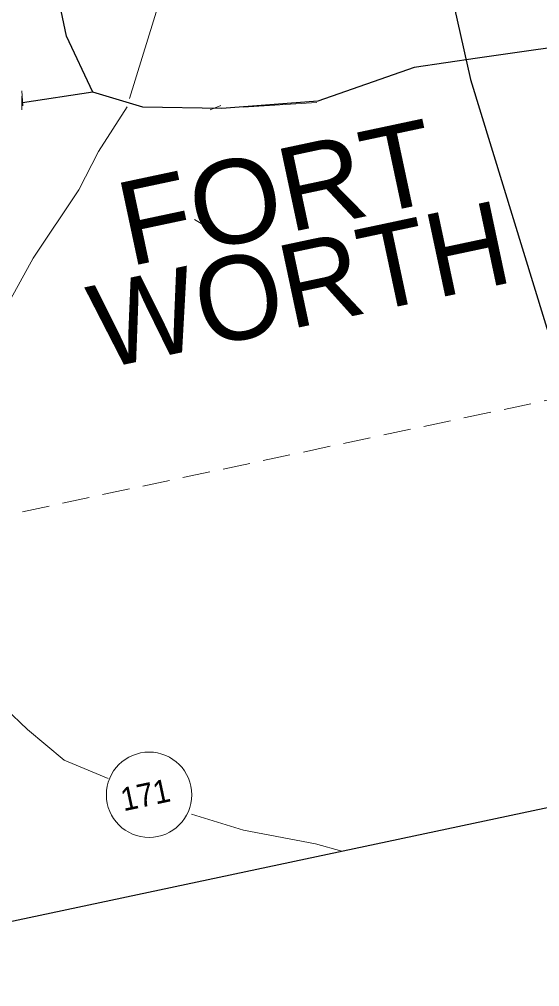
# Model space of a CAD drawing. Extents: x 2357218 to 2371708, y 6973728 to 6980157.
# Drawn here: x 2357408.8 to 2357522.9, y 6974407.9 to 6974620.2 of the extents above; entities that cross this region are included whole.
import ezdxf

# ---------------------------------------------------------------- set-up
doc = ezdxf.new("R2010")
doc.units = 0
doc.header["$LTSCALE"] = 2
doc.linetypes.add('MEDIUM_DASHED', pattern=[4.5, 3, -1.5])
doc.layers.add('62', color=7, linetype='Continuous', lineweight=13)
doc.layers.add('63', color=7, linetype='Continuous', lineweight=13)

msp = doc.modelspace()

# ---------------------------------------------------------------- linework, layer by layer
at = {"layer": '62'}
for p, q in [((2357440.151, 6974626.169), (2357432.971, 6974602.904)), ((2357409.331, 6974604.592), (2357409.526, 6974601.301)), ((2357409.315, 6974603.372), (2357409.369, 6974600.416)), ((2357450.639, 6974600.423), (2357452.946, 6974601.374)), ((2357474.001, 6974601.984), (2357457.839, 6974600.965)), ((2357449.732, 6974574.81), (2357447.205, 6974576.321)), ((2357410.579, 6974464.416), (2357418.634, 6974457.686)), ((2357418.634, 6974457.686), (2357428.242, 6974453.609)), ((2357457.93, 6974442.297), (2357446.564, 6974445.791))]:
    msp.add_line(p, q, dxfattribs=at)
at = {"layer": '62', "lineweight": 25}
msp.add_line((2357424.93, 6974604.275), (2357409.493, 6974601.89), dxfattribs=at)
at = {"layer": '62', "linetype": 'MEDIUM_DASHED'}
msp.add_line((2357321.423, 6974493.477), (2357761.192, 6974586.953), dxfattribs=at)
at = {"layer": '62', "lineweight": 25}
for points in [[(2357242.867, 6974863.05), (2357339.603, 6974407.945), (2357779.37, 6974501.42), (2357682.634, 6974956.528)], [(2357484.401, 6974709.004), (2357495.501, 6974661.441), (2357507.761, 6974607.022), (2357528.73, 6974538.67), (2357551.355, 6974511.341)], [(2357596.715, 6974637.66), (2357589.374, 6974634.536), (2357579.785, 6974631.6), (2357566.27, 6974627.645), (2357556.498, 6974625.57), (2357549.681, 6974623.223), (2357545.38, 6974619.435), (2357535.992, 6974615.437), (2357522.037, 6974613.553), (2357509.283, 6974611.762), (2357495.348, 6974609.674), (2357474.275, 6974602.318), (2357453.198, 6974600.715), (2357435.858, 6974601.009), (2357424.93, 6974604.275), (2357419.167, 6974616.556), (2357416.416, 6974629.495), (2357413.211, 6974635.486), (2357416.135, 6974645.654)]]:
    msp.add_lwpolyline(points, dxfattribs=at)
at = {"layer": '62'}
for points in [[(2357432.423, 6974601.035), (2357426.152, 6974591.262), (2357421.824, 6974582.844), (2357411.809, 6974567.829), (2357403.224, 6974552.273)], [(2357309.219, 6974550.9), (2357313.892, 6974547.2), (2357327.315, 6974535.032), (2357335.518, 6974519.384), (2357342.091, 6974506.75), (2357351.934, 6974500.263), (2357369.659, 6974490.04), (2357379.731, 6974485.624), (2357395.823, 6974478.418), (2357410.579, 6974464.416)], [(2357457.93, 6974442.297), (2357473.727, 6974439.306), (2357479.502, 6974437.68)]]:
    msp.add_lwpolyline(points, dxfattribs=at)
msp.add_circle((2357437.237, 6974450.059), 9.364, dxfattribs=at)
at = {"layer": '63'}
for p, q in [((2357440.151, 6974626.169), (2357432.971, 6974602.904)), ((2357409.331, 6974604.592), (2357409.526, 6974601.301)), ((2357409.315, 6974603.372), (2357409.369, 6974600.416)), ((2357450.639, 6974600.423), (2357452.946, 6974601.374)), ((2357474.001, 6974601.984), (2357457.839, 6974600.965)), ((2357449.732, 6974574.81), (2357447.205, 6974576.321)), ((2357410.579, 6974464.416), (2357418.634, 6974457.686)), ((2357418.634, 6974457.686), (2357428.242, 6974453.609)), ((2357457.93, 6974442.297), (2357446.564, 6974445.791))]:
    msp.add_line(p, q, dxfattribs=at)
at = {"layer": '63', "lineweight": 25}
msp.add_line((2357424.93, 6974604.275), (2357409.493, 6974601.89), dxfattribs=at)
at = {"layer": '63', "linetype": 'MEDIUM_DASHED'}
msp.add_line((2357321.423, 6974493.477), (2357761.192, 6974586.953), dxfattribs=at)
at = {"layer": '63', "lineweight": 25}
for points in [[(2357242.867, 6974863.05), (2357339.603, 6974407.945), (2357779.37, 6974501.42), (2357682.634, 6974956.528)], [(2357484.401, 6974709.004), (2357495.501, 6974661.441), (2357507.761, 6974607.022), (2357528.73, 6974538.67), (2357551.355, 6974511.341)], [(2357596.715, 6974637.66), (2357589.374, 6974634.536), (2357579.785, 6974631.6), (2357566.27, 6974627.645), (2357556.498, 6974625.57), (2357549.681, 6974623.223), (2357545.38, 6974619.435), (2357535.992, 6974615.437), (2357522.037, 6974613.553), (2357509.283, 6974611.762), (2357495.348, 6974609.674), (2357474.275, 6974602.318), (2357453.198, 6974600.715), (2357435.858, 6974601.009), (2357424.93, 6974604.275), (2357419.167, 6974616.556), (2357416.416, 6974629.495), (2357413.211, 6974635.486), (2357416.135, 6974645.654)]]:
    msp.add_lwpolyline(points, dxfattribs=at)
at = {"layer": '63'}
for points in [[(2357432.423, 6974601.035), (2357426.152, 6974591.262), (2357421.824, 6974582.844), (2357411.809, 6974567.829), (2357403.224, 6974552.273)], [(2357309.219, 6974550.9), (2357313.892, 6974547.2), (2357327.315, 6974535.032), (2357335.518, 6974519.384), (2357342.091, 6974506.75), (2357351.934, 6974500.263), (2357369.659, 6974490.04), (2357379.731, 6974485.624), (2357395.823, 6974478.418), (2357410.579, 6974464.416)], [(2357457.93, 6974442.297), (2357473.727, 6974439.306), (2357479.502, 6974437.68)]]:
    msp.add_lwpolyline(points, dxfattribs=at)
msp.add_circle((2357437.237, 6974450.059), 9.364, dxfattribs=at)

# ---------------------------------------------------------------- texts
at = {"layer": '62'}
for s, height, width, p in [('FORT', 18.39, 1.05, (2357432.817, 6974565.97)), ('171', 5.099, 0.95, (2357431.657, 6974446.423))]:
    msp.add_text(s, height=height, rotation=12, dxfattribs=dict(at, width=width)).set_placement(p)
msp.add_text('WORTH', height=18.39, rotation=12, dxfattribs=at).set_placement((2357426.733, 6974543.398))
at = {"layer": '63'}
for s, height, width, p in [('FORT', 18.39, 1.05, (2357432.817, 6974565.97)), ('171', 5.099, 0.95, (2357431.657, 6974446.423))]:
    msp.add_text(s, height=height, rotation=12, dxfattribs=dict(at, width=width)).set_placement(p)
msp.add_text('WORTH', height=18.39, rotation=12, dxfattribs=at).set_placement((2357426.733, 6974543.398))

doc.saveas('drawing.dxf')
